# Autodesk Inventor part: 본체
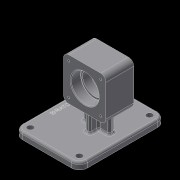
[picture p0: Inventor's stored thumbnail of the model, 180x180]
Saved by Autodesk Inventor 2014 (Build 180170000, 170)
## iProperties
Created: 2020-11
Part Number: 본체
Material: Generic
Document SubType Name: Modeling
Designer: kh
Density: 1 g/cm^3
Appearance: Default
Author: kh
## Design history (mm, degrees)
sketch "스케치1"
  geometry: L1 (65, 49)-(-65, 49); L2 (-65, 49)-(-65, -49); L3 (-65, -49)-(65, -49); L4 (65, -49)-(65, 49); L5 (65, 49)-(-65, -49); L6 (-65, 49)-(65, -49); 1 further point
  constraints: 12 end point, 2 midpoint, 2 parallel, 1 horizontal, 1 perpendicular
  dimensions: "d0" = 130 distance between parallel lines of L2 L4; "d1" = 98 distance between parallel lines of L1 L3
extrude "돌출1" new body sketch "스케치1" distance "d2" = 10; taper "d3" = 0 deg
sketch "스케치2"
  geometry: L1 (102, 45)-(38, 45); L2 (38, 45)-(38, -19); L3 (38, -19)-(102, -19); L4 (102, -19)-(102, 45); L5 (102, 45)-(38, -19); L6 (38, 45)-(102, -19); L7 (0, -49)-(10, -49) reference; 2 further points
  constraints: 12 end point, 2 midpoint, 2 parallel, 1 horizontal, 1 perpendicular
  dimensions: "d4" = 64 distance between parallel lines of L3 L1; "d5" = 70 horizontal distance of point (0, 0) point (70, 13); "d6" = 62 distance from line of L7 point (70, 13); "d7" = 64 distance between parallel lines of L2 L4
extrude "돌출2" join sketch "스케치2" stored distance "d8" = 42; taper "d9" = 0 deg
fillet "모깎기1" dims "d10" = 12
hole "구멍1" diameter "d13" = 9; stored, may be unused: countersink angle "d17" = 90 deg, drill point angle "d19" = 118 deg; dims "d11" = 10, "d12" = 10, "d14" = 6, "d15" = 4, "d16" = 2, "d18" = 8
fillet "모깎기2" dims "d24" = 8
sketch "스케치3"
  geometry: L1 (37, 102)-(-11, 102) reference; L2 (-19, 94)-(-19, 46) reference; 4 further points
  constraints: 2 midpoint, 1 horizontal alignment, 1 vertical alignment
hole "구멍2" sketch "스케치3" at (13, 70) diameter "d25" = 36; stored, may be unused: countersink angle "d29" = 90 deg, drill point angle "d31" = 118 deg; dims "d26" = 6, "d27" = 42, "d28" = 15, "d30" = 8
hole "구멍3" diameter "d34" = 42; stored, may be unused: countersink angle "d38" = 90 deg, drill point angle "d40" = 0 deg; dims "d32" = 10, "d33" = 10, "d35" = 6, "d36" = 42, "d37" = 15, "d39" = 15
fillet "모깎기3" dims "d41" = 0.3
chamfer "모따기1" distance "d42" = 1; stored, may be unused: second distance "d43" = 2, angle "d44" = 45 deg
sketch "스케치4"
  geometry: L1 (38, -7)-(10, -7); L2 (38, 33)-(10, 33); L3 (10, 37)-(10, -37) reference; L4 (38, 37)-(38, -11) reference; L5 (70, 13)-(-11.805, 13); L6 (38, -7)-(38, 33); L7 (10, -7)-(10, 33); C1 r 18 at (70, 13) reference; 1 further point
  constraints: 10 end point, 4 point on line, 2 parallel, 1 collinear, 1 horizontal, 1 perpendicular, 1 other
  dimensions: "d45" = 40 distance between parallel lines of L2 L1
extrude "돌출3" join sketch "스케치4" stored distance "d46" = 8; taper "d47" = 0 deg
node "작업 평면1"
sketch "스케치5"
  geometry: L1 (-13, 31.88)-(-13, -5.248); 1 further point
  constraints: 2 end point, 1 vertical
  dimensions: "d48" = 17 distance from line of point (4, -10) L1
feature "리브1" sketch "스케치5" dims "d49" = 1, "d50" = 8, "d51" = 0, "d52" = 0, "d53" = 1, "d54" = 1
hole "구멍4" diameter "d57" = 3.242; stored, may be unused: countersink angle "d61" = 90 deg, drill point angle "d63" = 118 deg; dims "d55" = 10, "d56" = 10, "d58" = 8, "d59" = 42, "d60" = 15, "d62" = 10
fillet "모깎기4" dims "d68" = 3
fillet "모깎기5" dims "d69" = 3
fillet "모깎기6" dims "d70" = 3
sketch "스케치6"
  geometry: L1 (53, 49)-(-53, 49) reference; L2 (65, -37)-(65, 37) reference; 3 further points
  constraints: 1 midpoint, 1 vertical alignment, 1 other
  dimensions: "d71" = 10 distance from line of point (0, 39) L1
feature "엠보싱1" sketch "스케치6" dims "d0" = 130, "d1" = 98, "d73" = 0.5, "d74" = 0
node "솔리드1"
pattern_linear "직사각형 패턴1"
mirror "대칭1"
pattern_linear "직사각형 패턴2"
mirror "대칭2"
